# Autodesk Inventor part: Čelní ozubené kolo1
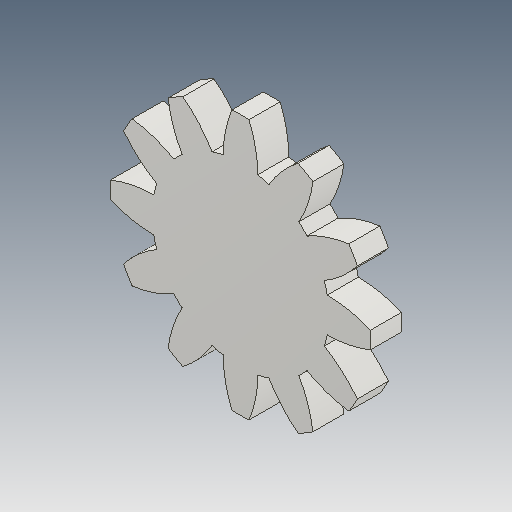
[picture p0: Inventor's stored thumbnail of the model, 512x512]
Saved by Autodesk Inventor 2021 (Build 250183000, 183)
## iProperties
Created: 2024-11
Part Number: Čelní ozubené kolo1
Material: Steel
Document SubType Name: Modeling
Designer: tatulinek
Categories: <?xml version="1.0" encoding="UTF-16"?> <MemberInstance><Categories><FamilyTemplate><FamilyTemplateParameter ValueType="xs:double" Id="1" ObjectReferenceKey="da
Density: 1 g/cm^3
Appearance: Steel
CustomPartVersion: 1
Author: tatulinek
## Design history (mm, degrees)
sketch "Sketch1"
  geometry: C1 r 83.988 at (0, 0)
  constraints: 1 centre point
  dimensions: "d0" = 167.97615 diameter of C1 (= da_da)
extrude "Extrusion1" new body sketch "Sketch1" distance "d1" = 20 (= da_b); taper "d2" = 0 deg
workplane "Work Plane2"
sketch "Sketch2"
  geometry: C1 r 83.988 at (0, 0) reference; C2 r 72 at (0, 0)
  constraints: 1 centre point, 1 coincident
  dimensions: "d3" = 144 diameter of C2 (= da_d)
feature "Roztečný průměr" sketch "Sketch2" dims "d4" = 10, "d5" = 0
workplane "Work Plane8"
workplane "Work Plane9"
feature "Čelní ozubené kolo" dims "d5" = 0, "da_b" = 20, "da_d" = 144, "da_aw" = 174.747, "da_da" = 167.97615, "da_df" = 114, "da_dw" = 144.61821, angle "da_beta" = 0 deg, "da_lefttooth" = 0, "da_righttooth" = 0
body "Solid1"
body "Srf1"
other parameters: "d16" = 174.747 (= da_aw), "d17" = 0, "d34" = 15 deg (computed from da_z), "d39" = 0, "d41" = 0, "d43" = 174.747 (= da_aw), "d46" = 174.747 (= da_aw), "d47" = 0, "d48" = 0
